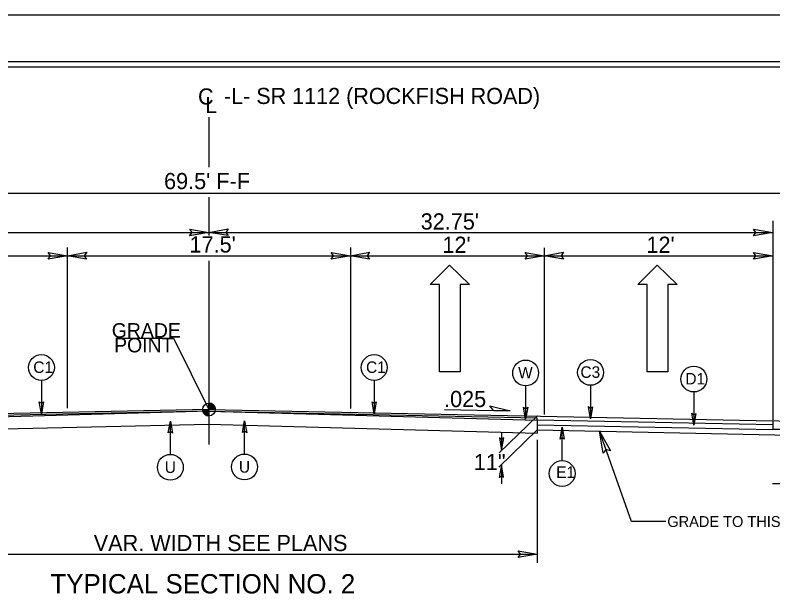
# Model space of a CAD drawing. Extents: x 958711 to 962106, y 831169 to 840840.
# Drawn here: x 959401.6 to 959766.7, y 839333.5 to 839615.4 of the extents above; entities that cross this region are included whole.
import ezdxf

# ---------------------------------------------------------------- set-up
doc = ezdxf.new("R2010")
doc.units = 0
for name, color, linetype in [('Default', 7, 'Continuous'), ('Old_Level_1', 7, 'Continuous'), ('Old_Level_11', 7, 'Continuous'), ('Old_Level_3', 7, 'Continuous'), ('Prop Dimension Text', 7, 'Continuous'), ('Prop Lane Arrow CELL', 7, 'Continuous'), ('Sheet Plot Border Inside CELL', 7, 'Continuous'), ('Sheet Plot Border Outside CELL', 7, 'Continuous'), ('Sheet Typical CELL', 7, 'Continuous'), ('Typical ID Circle CELL', 7, 'Continuous'), ('Typical Terminator CELL', 7, 'Continuous'), ('Typical Text Grade Point CELL', 7, 'Continuous'), ('Typical Text ID Circle CELL', 7, 'Continuous')]:
    doc.layers.add(name, color=color, linetype=linetype)

# ---------------------------------------------------------------- blocks, each defined once
blk = doc.blocks.new('Lane Arrow Through')
at = {"layer": 'Prop Lane Arrow CELL'}
for p, q in [((-3.15, 1.6), (-3.15, 3.1)), ((-3.15, 3.1), (0, 0)), ((-17.15, 1.6), (-3.15, 1.6)), ((-17.15, -1.7), (-17.15, 1.6)), ((0, 0), (-3.15, -3.2)), ((-3.15, -1.7), (-17.15, -1.7)), ((-3.15, -3.2), (-3.15, -1.7))]:
    blk.add_line(p, q, dxfattribs=at)

msp = doc.modelspace()

# ---------------------------------------------------------------- linework, layer by layer
at = {"layer": 'Default'}
for p, q in [((959494.95, 839566.21), (959494.95, 839542.07)), ((959494.95, 839527.58), (959494.95, 839509.23)), ((959494.95, 839497.02), (959494.95, 839408.38))]:
    msp.add_line(p, q, dxfattribs=at)
at = {"layer": 'Old_Level_1'}
for p, q in [((959213.41, 839529.55), (959779.86, 839529.55)), ((959766.65, 839516.25), (959766.65, 839420.28)), ((959766.65, 839516.25), (959766.65, 839420.77)), ((959226.62, 839510.66), (959494.95, 839510.66)), ((959494.95, 839510.66), (959766.65, 839510.66)), ((959426.79, 839425.88), (959426.79, 839503.33)), ((959563.12, 839503.33), (959563.12, 839425.73)), ((959656.6, 839503.17), (959656.6, 839422.88)), ((959333.31, 839499.42), (959426.79, 839499.42)), ((959426.79, 839499.42), (959563.12, 839499.42)), ((959563.12, 839499.42), (959656.6, 839499.42)), ((959656.6, 839499.42), (959766.65, 839499.42)), ((959494.95, 839425.26), (959494.95, 839428.33)), ((959494.95, 839425.26), (959226.62, 839419.83)), ((959494.95, 839424.4), (959332.23, 839419.96)), ((959494.94, 839424.4), (959332.23, 839421.1)), ((959491.89, 839425.26), (959494.95, 839425.26)), ((959494.95, 839425.26), (959766.65, 839419.77)), ((959498.01, 839425.26), (959494.95, 839425.26)), ((959494.95, 839422.21), (959494.95, 839425.26)), ((959494.95, 839425.26), (959494.95, 839422.21)), ((959494.95, 839424.4), (959653.23, 839421.2)), ((959608.47, 839425.2), (959640.07, 839424.56)), ((959653.26, 839422.24), (959634.78, 839404.31)), ((959653.23, 839420.08), (959653.23, 839421.2)), ((959653.23, 839420.33), (959766.65, 839418.04)), ((959653.23, 839420.08), (959653.23, 839413.89)), ((959653.23, 839417.91), (959766.65, 839415.61)), ((959653.23, 839415.41), (959634.76, 839397.48)), ((959636, 839413.84), (959636, 839405.48)), ((959653.23, 839415.41), (959789.59, 839412.65)), ((959698.58, 839371.22), (959683.27, 839414.8)), ((959653.23, 839410.65), (959653.23, 839351.4)), ((959635.93, 839398.66), (959635.93, 839389.44)), ((959783.22, 839389.47), (959766.62, 839389.47)), ((959715.19, 839371.22), (959698.58, 839371.22)), ((959332.23, 839355.52), (959653.23, 839355.52))]:
    msp.add_line(p, q, dxfattribs=at)
for points in [[(959494.99, 839428.33), (959494.99, 839428.33), (959494.99, 839425.26)], [(959495.04, 839428.33), (959495.04, 839425.26)], [(959495.1, 839428.32), (959495.1, 839425.26)], [(959495.17, 839428.31), (959495.17, 839425.26)], [(959495.23, 839428.31), (959495.23, 839425.26)], [(959495.29, 839428.31), (959495.29, 839425.26)], [(959495.36, 839428.3), (959495.36, 839425.26)], [(959495.42, 839428.3), (959495.42, 839425.26)], [(959495.47, 839428.27), (959495.47, 839425.26)], [(959495.53, 839428.27), (959495.53, 839425.26)], [(959495.6, 839428.26), (959495.6, 839425.26)], [(959495.66, 839428.24), (959495.66, 839425.26)], [(959495.72, 839428.22), (959495.72, 839425.26)], [(959495.78, 839428.21), (959495.78, 839425.26)], [(959495.85, 839428.19), (959495.85, 839425.26)], [(959495.9, 839428.17), (959495.9, 839425.26)], [(959495.97, 839428.15), (959495.96, 839425.26)], [(959496.02, 839428.13), (959496.02, 839425.26)], [(959496.08, 839428.11), (959496.08, 839425.26)], [(959496.15, 839428.08), (959496.15, 839425.26)], [(959496.21, 839428.06), (959496.21, 839425.26)], [(959496.27, 839428.02), (959496.27, 839425.26)], [(959496.33, 839428), (959496.33, 839425.26)], [(959496.39, 839427.98), (959496.39, 839425.26)], [(959496.45, 839427.94), (959496.45, 839425.26)], [(959496.52, 839427.9), (959496.52, 839425.26)], [(959496.58, 839427.86), (959496.58, 839425.26)], [(959496.64, 839427.82), (959496.64, 839425.26)], [(959496.7, 839427.77), (959496.7, 839425.26)], [(959496.75, 839427.74), (959496.75, 839425.26)], [(959496.82, 839427.69), (959496.82, 839425.26)], [(959496.88, 839427.64), (959496.88, 839425.26)], [(959496.94, 839427.6), (959496.94, 839425.26)], [(959497, 839427.54), (959497, 839425.26)], [(959497.06, 839427.48), (959497.06, 839425.26)], [(959497.13, 839427.42), (959497.13, 839425.26)], [(959497.19, 839427.36), (959497.19, 839425.26)], [(959497.25, 839427.29), (959497.25, 839425.26)], [(959497.31, 839427.23), (959497.31, 839425.26)], [(959497.37, 839427.14), (959497.37, 839425.26)], [(959497.44, 839427.06), (959497.44, 839425.26)], [(959497.5, 839426.98), (959497.5, 839425.26)], [(959491.91, 839425.26), (959491.91, 839424.94)], [(959491.98, 839425.26), (959491.98, 839424.58)], [(959492.04, 839425.26), (959492.04, 839424.36)], [(959492.1, 839425.26), (959492.1, 839424.17)], [(959492.17, 839425.26), (959492.17, 839424.03)], [(959492.23, 839425.26), (959492.23, 839423.9)], [(959492.28, 839425.26), (959492.28, 839423.79)], [(959492.34, 839425.26), (959492.34, 839423.67)], [(959492.41, 839425.26), (959492.41, 839423.59)], [(959492.47, 839425.26), (959492.47, 839423.5)], [(959492.53, 839425.26), (959492.53, 839423.41)], [(959492.59, 839425.26), (959492.59, 839423.34)], [(959492.65, 839425.26), (959492.65, 839423.27)], [(959492.7, 839425.26), (959492.7, 839423.19)], [(959492.77, 839425.26), (959492.77, 839423.13)], [(959492.83, 839425.26), (959492.83, 839423.07)], [(959492.89, 839425.26), (959492.89, 839423.02)], [(959492.96, 839425.26), (959492.96, 839422.96)], [(959493.02, 839425.26), (959493.02, 839422.91)], [(959493.08, 839425.26), (959493.08, 839422.85)], [(959493.14, 839425.26), (959493.14, 839422.81)], [(959493.2, 839425.26), (959493.2, 839422.77)], [(959493.26, 839425.26), (959493.26, 839422.73)], [(959493.32, 839425.26), (959493.32, 839422.68)], [(959493.39, 839425.26), (959493.39, 839422.64)], [(959493.45, 839425.26), (959493.45, 839422.6)], [(959493.51, 839425.26), (959493.51, 839422.57)], [(959493.56, 839425.26), (959493.56, 839422.56)], [(959493.62, 839425.26), (959493.62, 839422.52)], [(959493.69, 839425.26), (959493.69, 839422.48)], [(959493.75, 839425.26), (959493.75, 839422.46)], [(959493.81, 839425.26), (959493.81, 839422.43)], [(959493.87, 839425.26), (959493.87, 839422.41)], [(959493.94, 839425.26), (959493.94, 839422.39)], [(959493.99, 839425.26), (959493.99, 839422.37)], [(959494.06, 839425.26), (959494.06, 839422.35)], [(959494.12, 839425.26), (959494.12, 839422.33)], [(959494.18, 839425.26), (959494.18, 839422.31)], [(959494.24, 839425.26), (959494.24, 839422.3)], [(959494.3, 839425.26), (959494.3, 839422.28)], [(959494.37, 839425.26), (959494.37, 839422.27)], [(959494.42, 839425.26), (959494.42, 839422.27)], [(959494.48, 839425.26), (959494.48, 839422.25)], [(959494.54, 839425.26), (959494.54, 839422.23)], [(959494.61, 839425.26), (959494.61, 839422.23)], [(959494.67, 839425.26), (959494.67, 839422.23)], [(959494.73, 839425.26), (959494.73, 839422.21)], [(959494.79, 839425.26), (959494.79, 839422.21)], [(959494.85, 839425.26), (959494.85, 839422.21)], [(959494.91, 839425.26), (959494.91, 839422.21), (959494.91, 839422.21)], [(959494.95, 839424.4), (959653.23, 839420.08)], [(959497.56, 839426.88), (959497.56, 839425.26)], [(959497.61, 839426.78), (959497.61, 839425.26)], [(959497.67, 839426.67), (959497.67, 839425.26)], [(959497.73, 839426.53), (959497.73, 839425.26)], [(959497.8, 839426.38), (959497.8, 839425.26)], [(959497.86, 839426.22), (959497.86, 839425.26)], [(959497.92, 839426.01), (959497.92, 839425.26)], [(959497.98, 839425.71), (959497.98, 839425.26)], [(959332.23, 839414.51), (959494.95, 839418.21)], [(959494.95, 839418.21), (959653.23, 839413.89)]]:
    msp.add_lwpolyline(points, dxfattribs=at)
msp.add_circle((959494.96, 839425.27), 3.06, dxfattribs=at)
for start, end in [(359.9905, 89.9905), (179.9905, 269.9905)]:
    msp.add_arc((959494.96, 839425.27), 3.06, start, end, dxfattribs=at)
at = {"layer": 'Old_Level_11'}
for p, q in [((959632.07, 839424.72), (959630.34, 839426.98)), ((959630.34, 839426.98), (959640.07, 839424.56)), ((959640.07, 839424.56), (959632.07, 839424.72))]:
    msp.add_line(p, q, dxfattribs=at)
msp.add_lwpolyline([(959684.96, 839404.21), (959683.27, 839414.8), (959688.48, 839405.35), (959686.28, 839406.03)], close=True, dxfattribs=at)
at = {"layer": 'Old_Level_3'}
for p, q in [((959778.19, 839419.19), (959766.65, 839419.77)), ((959766.65, 839419.77), (959766.65, 839415.78)), ((959766.65, 839415.78), (959783.22, 839415.78))]:
    msp.add_line(p, q, dxfattribs=at)
at = {"layer": 'Sheet Plot Border Inside CELL'}
msp.add_lwpolyline([(960390.3, 839592.94), (958723.8, 839592.94), (958723.8, 838537.84), (960390.3, 838537.84)], close=True, dxfattribs=at)
at = {"layer": 'Sheet Plot Border Outside CELL'}
msp.add_lwpolyline([(960394.8, 839615.39), (958710.8, 839615.39), (958710.8, 838515.39), (960394.8, 838515.39)], close=True, dxfattribs=at)
at = {"layer": 'Sheet Typical CELL'}
msp.add_lwpolyline([(960377.8, 839590.39), (958877.8, 839590.39), (958877.8, 838540.39), (960377.8, 838540.39)], close=True, dxfattribs=at)
at = {"layer": 'Typical ID Circle CELL'}
for p, q in [((959414.24, 839439.29), (959414.24, 839423.2)), ((959574.6, 839439.29), (959574.6, 839423.2)), ((959647.6, 839436.66), (959647.6, 839420.57)), ((959678.9, 839436.94), (959678.9, 839420.85)), ((959728.67, 839433.74), (959728.67, 839417.65)), ((959476.39, 839403.62), (959476.39, 839419.71)), ((959512.13, 839403.79), (959512.13, 839419.88)), ((959665.21, 839400.64), (959665.21, 839416.72))]:
    msp.add_line(p, q, dxfattribs=at)
for centre in [(959414.24, 839445.52), (959574.6, 839445.52), (959647.6, 839442.88), (959678.9, 839443.16), (959728.67, 839439.96), (959476.39, 839397.4), (959512.13, 839397.57), (959665.21, 839394.41)]:
    msp.add_circle(centre, 6.23, dxfattribs=at)
at = {"layer": 'Typical Terminator CELL'}
for points in [[(959485.73, 839512.25), (959494.95, 839510.66), (959485.68, 839509.02), (959486.86, 839510.66)], [(959504.18, 839509.08), (959494.95, 839510.66), (959504.23, 839512.3), (959503.05, 839510.66)], [(959757.43, 839512.25), (959766.65, 839510.66), (959757.38, 839509.02), (959758.55, 839510.66)], [(959417.57, 839501.01), (959426.79, 839499.42), (959417.52, 839497.78), (959418.7, 839499.42)], [(959436.01, 839497.83), (959426.79, 839499.42), (959436.06, 839501.06), (959434.89, 839499.42)], [(959553.89, 839501.01), (959563.12, 839499.42), (959553.84, 839497.78), (959555.02, 839499.42)], [(959572.34, 839497.83), (959563.12, 839499.42), (959572.39, 839501.06), (959571.21, 839499.42)], [(959647.37, 839501.01), (959656.6, 839499.42), (959647.32, 839497.78), (959648.5, 839499.42)], [(959665.82, 839497.83), (959656.6, 839499.42), (959665.87, 839501.06), (959664.69, 839499.42)], [(959757.43, 839501.01), (959766.65, 839499.42), (959757.38, 839497.78), (959758.55, 839499.42)], [(959415.24, 839428.97), (959414.24, 839423.2), (959413.22, 839429), (959414.24, 839428.26)], [(959575.59, 839428.97), (959574.6, 839423.2), (959573.58, 839429), (959574.6, 839428.26)], [(959648.59, 839426.34), (959647.6, 839420.57), (959646.57, 839426.37), (959647.6, 839425.63)], [(959679.89, 839426.61), (959678.9, 839420.85), (959677.87, 839426.65), (959678.9, 839425.91)], [(959729.66, 839423.42), (959728.67, 839417.65), (959727.65, 839423.45), (959728.67, 839422.71)], [(959475.4, 839413.95), (959476.39, 839419.71), (959477.41, 839413.92), (959476.39, 839414.65)], [(959511.14, 839414.11), (959512.13, 839419.88), (959513.16, 839414.08), (959512.13, 839414.82)], [(959664.22, 839410.96), (959665.21, 839416.72), (959666.24, 839410.93), (959665.21, 839411.66)], [(959634.95, 839411.55), (959636, 839405.48), (959637.07, 839411.58), (959636, 839410.81)], [(959636.98, 839392.59), (959635.93, 839398.66), (959634.85, 839392.56), (959635.93, 839393.33)], [(959644.01, 839357.11), (959653.23, 839355.52), (959643.96, 839353.88), (959645.14, 839355.52)]]:
    msp.add_lwpolyline(points, close=True, dxfattribs=at)
at = {"layer": 'Typical Text Grade Point CELL'}
for p, q in [((959452.51, 839459.65), (959477.84, 839459.65)), ((959477.84, 839459.65), (959494.95, 839425.26))]:
    msp.add_line(p, q, dxfattribs=at)

# ---------------------------------------------------------------- block references
at = {"layer": 'Old_Level_1', "xscale": 3, "yscale": 3, "rotation": 90}
for p in [(959610.96, 839494.92), (959710.96, 839494.92)]:
    msp.add_blockref('Lane Arrow Through', p, dxfattribs=at)

# ---------------------------------------------------------------- texts
at = {"layer": 'Old_Level_1'}
for s, height, p in [('GRADE TO THIS LINE', 5.2473, (959715.87, 839368.63)), ('TYPICAL SECTION NO. 2', 9.3239, (959418.6, 839336.59))]:
    msp.add_text(s, height=height, dxfattribs=at).set_placement(p)
at = {"layer": 'Old_Level_11'}
for s, height, p in [('GRADE', 7, (959448.15, 839459.9)), ('POINT', 7, (959449.29, 839452.83)), ('11"', 7.801, (959622.62, 839396.04))]:
    msp.add_text(s, height=height, dxfattribs=at).set_placement(p)
at = {"layer": 'Prop Dimension Text'}
for s, height, rotation, p in [('-L- SR 1112 (ROCKFISH ROAD)', 7.7675, 0, (959502.2, 839572.56)), ('C', 7.77, 0, (959489.71, 839572.3)), ('L', 7.77, 0, (959493.11, 839568.2)), ("69.5' F-F", 7.801, 0, (959473.34, 839531.51)), ("32.75'", 7.801, 0, (959597.02, 839512.04)), ("17.5'", 7.801, 0, (959485.61, 839500.95)), ("12'", 7.801, 0, (959607.5, 839500.8)), ("12'", 7.801, 0, (959705.82, 839500.8)), ('.025', 7.801, 360, (959608.28, 839426.44)), ('VAR. WIDTH SEE PLANS', 7.8009, 0, (959439.45, 839357.02))]:
    msp.add_text(s, height=height, rotation=rotation, dxfattribs=at).set_placement(p)
at = {"layer": 'Typical Text ID Circle CELL'}
for s, height, p in [('C1', 5.572, (959410.33, 839442.89)), ('C1', 5.572, (959570.69, 839442.89)), ('W', 5.57, (959643.98, 839440.25)), ('C3', 5.572, (959674.01, 839440.53)), ('D1', 5.572, (959724.59, 839437.33)), ('U', 5.57, (959473.69, 839394.66)), ('U', 5.57, (959509.43, 839394.82)), ('E1', 5.572, (959662.33, 839392.28))]:
    msp.add_text(s, height=height, dxfattribs=at).set_placement(p)

doc.saveas('drawing.dxf')
